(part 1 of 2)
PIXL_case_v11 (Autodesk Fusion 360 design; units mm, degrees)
part number: 0.96Oled_W_4_Buttons
base_feature "Base Feature"
sketch "Sketch2" plane through (-14.9, 0, 0) normal (1, 0, 0) x axis (0, 1, 0)
  line L1 (-22, 2.8) -> (-14, 2.8)
  line L2 (-22, -6.3) -> (-22, 2.8)
  line L3 (-14, -6.3) -> (-22, -6.3)
  line L4 (-14, 2.8) -> (-14, -6.3)
  line L5 (-20.5, -3.5) -> (-15.5, -3.5)
  line L6 (-20.5, 0) -> (-20.5, -3.5)
  line L7 (-15.5, 0) -> (-20.5, 0)
  line L8 (-15.5, -3.5) -> (-15.5, 0)
  horizontal L5
  vertical L6
  horizontal L7
  vertical L8
sketch "Sketch3" plane through (-22.2, 0, 0) normal (1, 0, 0) x axis (0, 1, 0)
  line L1 (12, -6.5) -> (-23.8, -6.5)
  line L2 (12, 2.8) -> (12, -6.5)
  line L3 (-14, 2.8) -> (12, 2.8)
  line L4 (-14, -6.3) -> (-14, 2.8)
  line L5 (-14.9, -6.3) -> (-14, -6.3)
  line L6 (-14.9, 2.8) -> (-14.9, -6.3)
  line L7 (-21.1, 2.8) -> (-14.9, 2.8)
  line L8 (-21.1, -6.3) -> (-21.1, 2.8)
  line L9 (-22, -6.3) -> (-21.1, -6.3)
  line L10 (-22, 2.8) -> (-22, -6.3)
  line L11 (-23.8, 2.8) -> (-22, 2.8)
  line L12 (-23.8, -6.5) -> (-23.8, 2.8)
  line L13 (-13.4, -1.2) -> (-13.4, -3.2)
  line L14 (-7.6, -1.2) -> (-13.4, -1.2)
  line L15 (-7.6, -3.2) -> (-7.6, -1.2)
  line L16 (-13.4, -3.2) -> (-7.6, -3.2)
  line L17 (-15.5, -1) -> (-20.5, -1)
  line L18 (-15.5, -5) -> (-15.5, -1)
  line L19 (-20.5, -5) -> (-15.5, -5)
  line L20 (-20.5, -1) -> (-20.5, -5)
  line L21 (-15.5, -5) -> (-20.5, -1)
  line L22 (-20.5, -5) -> (-15.5, -1)
  point P22 (-18, -3)
  horizontal L17
  perpendicular L17 L18
  parallel L17 L19
  parallel L18 L20
  coincident L21 P22
  coincident L22 P22
sketch "Sketch4" plane through (-24.2, 0, 0) normal (-1, 0, 0) x axis (0, -1, 0)
  line L1 (15.5, -2) -> (15.5, -4)
  line L2 (19.5, -1) -> (16.5, -1)
  line L3 (20.5, -4) -> (20.5, -2)
  line L4 (16.5, -5) -> (19.5, -5)
  line L5 (22.5, -6.5) -> (-10.7, -6.5)
  line L6 (22.5, 3.9) -> (22.5, -6.5)
  line L7 (-10.7, 3.9) -> (22.5, 3.9)
  line L8 (-10.7, -6.5) -> (-10.7, 3.9)
  line L9 (16.5, -4.747) -> (19.5, -4.747)
  line L10 (20.247, -4) -> (20.247, -2)
  line L11 (19.5, -1.253) -> (16.5, -1.253)
  line L12 (15.753, -2) -> (15.753, -4)
  arc A1 centre (16.5, -2) radius 1 clockwise from (15.5, -2) to (16.5, -1)
  arc A2 centre (19.5, -2) radius 1 clockwise from (19.5, -1) to (20.5, -2)
  arc A3 centre (19.5, -4) radius 1 clockwise from (20.5, -4) to (19.5, -5)
  arc A4 centre (16.5, -4) radius 1 clockwise from (16.5, -5) to (15.5, -4)
  arc A5 centre (16.5, -4) radius 0.747 clockwise from (16.5, -4.747) to (15.753, -4)
  arc A6 centre (19.5, -4) radius 0.747 clockwise from (20.247, -4) to (19.5, -4.747)
  arc A7 centre (19.5, -2) radius 0.747 clockwise from (19.5, -1.253) to (20.247, -2)
  arc A8 centre (16.5, -2) radius 0.747 clockwise from (15.753, -2) to (16.5, -1.253)
  dimension "d6918" = 0.253
extrude "Extrude1" new body sketch "Sketch4" profile of A5 L12 L11 L10 L9 A8 A7 A6 against normal blind 2.4
sketch "Sketch5" plane through (-21.8, 0, 0) normal (1, 0, 0) x axis (0, 1, 0)
  line L1 (-16.5, -4.747) -> (-19.5, -4.747)
  line L2 (-15.753, -2) -> (-15.753, -4)
  line L3 (-19.5, -1.253) -> (-16.5, -1.253)
  line L4 (-20.247, -4) -> (-20.247, -2)
  line L5 (-15.2226, -2) -> (-15.2226, -4)
  line L6 (-19.5, -0.7226) -> (-16.5, -0.7226)
  line L7 (-20.7774, -4) -> (-20.7774, -2)
  line L8 (-16.5, -5.2774) -> (-19.5, -5.2774)
  arc A1 centre (-19.5, -4) radius 0.747 clockwise from (-19.5, -4.747) to (-20.247, -4)
  arc A2 centre (-16.5, -4) radius 0.747 clockwise from (-15.753, -4) to (-16.5, -4.747)
  arc A3 centre (-16.5, -2) radius 0.747 clockwise from (-16.5, -1.253) to (-15.753, -2)
  arc A4 centre (-19.5, -2) radius 0.747 clockwise from (-20.247, -2) to (-19.5, -1.253)
  arc A5 centre (-16.5, -2) radius 1.2774 clockwise from (-16.5, -0.7226) to (-15.2226, -2)
  arc A6 centre (-19.5, -2) radius 1.2774 clockwise from (-20.7774, -2) to (-19.5, -0.7226)
  arc A7 centre (-19.5, -4) radius 1.2774 clockwise from (-19.5, -5.2774) to (-20.7774, -4)
  arc A8 centre (-16.5, -4) radius 1.2774 clockwise from (-15.2226, -4) to (-16.5, -5.2774)
  circle C1 centre (-18, -3) radius 0.7
  dimension "d6921" = 0.5304
extrude "Extrude2" add sketch "Sketch5" profile of A1 L1 A2 L2 A3 L3 A4 L4 L8 L6 L5 A8 A7 A6 A5 L7 against normal blind 0.2
extrude "Extrude3" add sketch "Sketch5" profile of C1 along normal blind 0.2
chamfer "Chamfer1" distance 0.2
extrude "Extrude4" add of existing geometry blind 0.6
sketch "Sketch6" plane through (-24.2, 0.0764, 0.0727) normal (-1, 0, 0) x axis (0, -1, 0)
  line L1 (15.5764, -2.0727) -> (15.5764, -4.0727)
  line L2 (19.5764, -1.0727) -> (16.5764, -1.0727)
  line L3 (20.5764, -4.0727) -> (20.5764, -2.0727)
  line L4 (16.5764, -5.0727) -> (19.5764, -5.0727)
  line L5 (22.5764, -6.5727) -> (-10.6236, -6.5727)
  line L6 (22.5764, 3.8273) -> (22.5764, -6.5727)
  line L7 (-10.6236, 3.8273) -> (22.5764, 3.8273)
  line L8 (-10.6236, -6.5727) -> (-10.6236, 3.8273)
  curve K1 (11.5332, -0.4103) -> (11.8143, -0.6915)
  curve K2 (11.252, -0.6915) -> (11.5332, -0.4103)
  line L9 (11.252, -3.2218) -> (11.252, -0.6915)
  curve K3 (11.5332, -3.503) -> (11.252, -3.2218)
  curve K4 (11.8143, -3.2218) -> (11.5332, -3.503)
  line L10 (11.8143, -0.6915) -> (11.8143, -3.2218)
  curve K5 (10.6893, -1.1174) -> (10.5799, -1.4996)
  curve K6 (10.307, -1.0079) -> (10.6893, -1.1174)
  curve K7 (9.0029, -3.2218) -> (10.307, -1.0079)
  curve K8 (11.5332, -5.7521) -> (9.0029, -3.2218)
  curve K9 (14.0635, -3.2218) -> (11.5332, -5.7521)
  curve K10 (12.7985, -1.0302) -> (14.0635, -3.2218)
  curve K11 (12.4144, -1.1328) -> (12.7985, -1.0302)
  curve K12 (12.517, -1.5169) -> (12.4144, -1.1328)
  curve K13 (13.5012, -3.2218) -> (12.517, -1.5169)
  curve K14 (11.5332, -5.1898) -> (13.5012, -3.2218)
  curve K15 (9.5652, -3.2218) -> (11.5332, -5.1898)
  curve K16 (10.5799, -1.4996) -> (9.5652, -3.2218)
  arc A1 centre (16.5764, -2.0727) radius 1 clockwise from (15.5764, -2.0727) to (16.5764, -1.0727)
  arc A2 centre (19.5764, -2.0727) radius 1 clockwise from (19.5764, -1.0727) to (20.5764, -2.0727)
  arc A3 centre (19.5764, -4.0727) radius 1 clockwise from (20.5764, -4.0727) to (19.5764, -5.0727)
  arc A4 centre (16.5764, -4.0727) radius 1 clockwise from (16.5764, -5.0727) to (15.5764, -4.0727)
work_plane "WorkPlane1" AlongDistance -6.5 ExtraOffset 0
sketch "Sketch1" plane through (0, 0, -6.5) normal (0, 0, 1) x axis (1, 0, 0)
  line L1 (24.2, -27.5) -> (-24.2, -27.5)
  line L2 (24.2, 15.7) -> (24.2, -27.5)
  line L3 (-24.2, 15.7) -> (24.2, 15.7)
  line L4 (-24.2, -27.5) -> (-24.2, 15.7)
extrude "Extrude1" new body sketch "Sketch1" along normal blind 11.8
fillet "Fillet1" radius 5
fillet "Fillet2" radius 1.4
work_plane "WorkPlane2" AlongDistance -6.5 ExtraOffset 0
sketch "Sketch2" plane through (0, 0, -6.5) normal (0, 0, 1) x axis (1, 0, 0)
  line L1 (22.2, -25.5) -> (-22.2, -25.5)
  line L2 (22.2, 13.7) -> (22.2, -25.5)
  line L3 (-22.2, 13.7) -> (22.2, 13.7)
  line L4 (-22.2, -25.5) -> (-22.2, 13.7)
extrude "Extrude2" cut sketch "Sketch2" along normal blind 9.3
fillet "Fillet3" radius 1.7
work_plane "WorkPlane3" AlongDistance 2.79 ExtraOffset 0
sketch "Sketch3" plane through (0, 0, 2.79) normal (0, 0, 1) x axis (1, 0, 0)
  line L1 (20.7, -11.3) -> (11, -11.3)
  line L2 (20.7, 11.7) -> (20.7, -11.3)
  line L3 (11, 11.7) -> (20.7, 11.7)
  line L4 (11, -11.3) -> (11, 11.7)
extrude "Extrude3" cut sketch "Sketch3" along normal blind 1.56
work_plane "WorkPlane4" AlongDistance 2.79 ExtraOffset 0
sketch "Sketch4" plane through (0, 0, 2.79) normal (0, 0, 1) x axis (1, 0, 0)
  line L1 (10, 9.6) -> (-10.8, 9.6)
  line L2 (10, 12.2) -> (10, 9.6)
  line L3 (-10.8, 12.2) -> (10, 12.2)
  line L4 (-10.8, 9.6) -> (-10.8, 12.2)
extrude "Extrude4" cut sketch "Sketch4" along normal blind 0.91
work_plane "WorkPlane5" AlongDistance 4.34 ExtraOffset 0
sketch "Sketch5" plane through (0, 0, 4.34) normal (0, 0, 1) x axis (1, 0, 0)
  line L1 (12.1, 5.6) -> (11.5, 5.6)
  line L2 (12.1, 11.8) -> (12.1, 5.6)
  line L3 (11.5, 11.8) -> (12.1, 11.8)
  line L4 (11.5, 5.6) -> (11.5, 11.8)
extrude "Extrude5" cut sketch "Sketch5" along normal blind 1.06
work_plane "WorkPlane6" AlongDistance 4.34 ExtraOffset 0
sketch "Sketch6" plane through (0, 0, 4.34) normal (0, 0, 1) x axis (1, 0, 0)
  line L1 (19.6, 11.2) -> (11.5, 11.2)
  line L2 (19.6, 11.8) -> (19.6, 11.2)
  line L3 (11.5, 11.8) -> (19.6, 11.8)
  line L4 (11.5, 11.2) -> (11.5, 11.8)
extrude "Extrude6" cut sketch "Sketch6" along normal blind 1.06
work_plane "WorkPlane7" AlongDistance 4.34 ExtraOffset 0
sketch "Sketch7" plane through (0, 0, 4.34) normal (0, 0, 1) x axis (1, 0, 0)
  line L1 (19.6, 5.6) -> (11.5, 5.6)
  line L2 (19.6, 6.2) -> (19.6, 5.6)
  line L3 (11.5, 6.2) -> (19.6, 6.2)
  line L4 (11.5, 5.6) -> (11.5, 6.2)
extrude "Extrude7" cut sketch "Sketch7" along normal blind 1.06
work_plane "WorkPlane8" AlongDistance 4.34 ExtraOffset 0
sketch "Sketch8" plane through (0, 0, 4.34) normal (0, 0, 1) x axis (1, 0, 0)
  line L1 (12.1, -0.07) -> (11.5, -0.07)
  line L2 (12.1, 6.13) -> (12.1, -0.07)
  line L3 (11.5, 6.13) -> (12.1, 6.13)
  line L4 (11.5, -0.07) -> (11.5, 6.13)
extrude "Extrude8" cut sketch "Sketch8" along normal blind 1.06
work_plane "WorkPlane9" AlongDistance 4.34 ExtraOffset 0
sketch "Sketch9" plane through (0, 0, 4.34) normal (0, 0, 1) x axis (1, 0, 0)
  line L1 (19.6, 5.53) -> (11.5, 5.53)
  line L2 (19.6, 6.13) -> (19.6, 5.53)
  line L3 (11.5, 6.13) -> (19.6, 6.13)
  line L4 (11.5, 5.53) -> (11.5, 6.13)
extrude "Extrude9" cut sketch "Sketch9" along normal blind 1.06
work_plane "WorkPlane10" AlongDistance 4.34 ExtraOffset 0
sketch "Sketch10" plane through (0, 0, 4.34) normal (0, 0, 1) x axis (1, 0, 0)
  line L1 (19.6, -0.07) -> (11.5, -0.07)
  line L2 (19.6, 0.53) -> (19.6, -0.07)
  line L3 (11.5, 0.53) -> (19.6, 0.53)
  line L4 (11.5, -0.07) -> (11.5, 0.53)
extrude "Extrude10" cut sketch "Sketch10" along normal blind 1.06
work_plane "WorkPlane11" AlongDistance 4.34 ExtraOffset 0
sketch "Sketch11" plane through (0, 0, 4.34) normal (0, 0, 1) x axis (1, 0, 0)
  line L1 (12.1, -5.73) -> (11.5, -5.73)
  line L2 (12.1, 0.47) -> (12.1, -5.73)
  line L3 (11.5, 0.47) -> (12.1, 0.47)
  line L4 (11.5, -5.73) -> (11.5, 0.47)
extrude "Extrude11" cut sketch "Sketch11" along normal blind 1.06
work_plane "WorkPlane12" AlongDistance 4.34 ExtraOffset 0
sketch "Sketch12" plane through (0, 0, 4.34) normal (0, 0, 1) x axis (1, 0, 0)
  line L1 (19.6, -0.13) -> (11.5, -0.13)
  line L2 (19.6, 0.47) -> (19.6, -0.13)
  line L3 (11.5, 0.47) -> (19.6, 0.47)
  line L4 (11.5, -0.13) -> (11.5, 0.47)
extrude "Extrude12" cut sketch "Sketch12" along normal blind 1.06
work_plane "WorkPlane13" AlongDistance 4.34 ExtraOffset 0
sketch "Sketch13" plane through (0, 0, 4.34) normal (0, 0, 1) x axis (1, 0, 0)
  line L1 (19.6, -5.73) -> (11.5, -5.73)
  line L2 (19.6, -5.13) -> (19.6, -5.73)
  line L3 (11.5, -5.13) -> (19.6, -5.13)
  line L4 (11.5, -5.73) -> (11.5, -5.13)
extrude "Extrude13" cut sketch "Sketch13" along normal blind 1.06
work_plane "WorkPlane14" AlongDistance 4.34 ExtraOffset 0
sketch "Sketch14" plane through (0, 0, 4.34) normal (0, 0, 1) x axis (1, 0, 0)
  line L1 (12.1, -11.4) -> (11.5, -11.4)
  line L2 (12.1, -5.2) -> (12.1, -11.4)
  line L3 (11.5, -5.2) -> (12.1, -5.2)
  line L4 (11.5, -11.4) -> (11.5, -5.2)
extrude "Extrude14" cut sketch "Sketch14" along normal blind 1.06
work_plane "WorkPlane15" AlongDistance 4.34 ExtraOffset 0
sketch "Sketch15" plane through (0, 0, 4.34) normal (0, 0, 1) x axis (1, 0, 0)
  line L1 (19.6, -5.8) -> (11.5, -5.8)
  line L2 (19.6, -5.2) -> (19.6, -5.8)
  line L3 (11.5, -5.2) -> (19.6, -5.2)
  line L4 (11.5, -5.8) -> (11.5, -5.2)
extrude "Extrude15" cut sketch "Sketch15" along normal blind 1.06
work_plane "WorkPlane16" AlongDistance 4.34 ExtraOffset 0
sketch "Sketch16" plane through (0, 0, 4.34) normal (0, 0, 1) x axis (1, 0, 0)
  line L1 (19.6, -11.4) -> (11.5, -11.4)
  line L2 (19.6, -10.8) -> (19.6, -11.4)
  line L3 (11.5, -10.8) -> (19.6, -10.8)
  line L4 (11.5, -11.4) -> (11.5, -10.8)
extrude "Extrude16" cut sketch "Sketch16" along normal blind 1.06
work_plane "WorkPlane17" AlongDistance 4.34 ExtraOffset 0
sketch "Sketch17" plane through (0, 0, 4.34) normal (0, 0, 1) x axis (1, 0, 0)
  line L1 (20.7, 6.2) -> (18.4, 6.2)
  line L2 (20.7, 11.2) -> (20.7, 6.2)
  line L3 (18.4, 11.2) -> (20.7, 11.2)
  line L4 (18.4, 6.2) -> (18.4, 11.2)
extrude "Extrude17" cut sketch "Sketch17" along normal blind 0.46
work_plane "WorkPlane18" AlongDistance 4.34 ExtraOffset 0
sketch "Sketch18" plane through (0, 0, 4.34) normal (0, 0, 1) x axis (1, 0, 0)
  line L1 (20.7, 0.53) -> (18.4, 0.53)
  line L2 (20.7, 5.53) -> (20.7, 0.53)
  line L3 (18.4, 5.53) -> (20.7, 5.53)
  line L4 (18.4, 0.53) -> (18.4, 5.53)
extrude "Extrude18" cut sketch "Sketch18" along normal blind 0.46
work_plane "WorkPlane19" AlongDistance 4.34 ExtraOffset 0
sketch "Sketch19" plane through (0, 0, 4.34) normal (0, 0, 1) x axis (1, 0, 0)
  line L1 (20.7, -5.13) -> (18.4, -5.13)
  line L2 (20.7, -0.13) -> (20.7, -5.13)
  line L3 (18.4, -0.13) -> (20.7, -0.13)
  line L4 (18.4, -5.13) -> (18.4, -0.13)
extrude "Extrude19" cut sketch "Sketch19" along normal blind 0.46
work_plane "WorkPlane20" AlongDistance 4.34 ExtraOffset 0
sketch "Sketch20" plane through (0, 0, 4.34) normal (0, 0, 1) x axis (1, 0, 0)
  line L1 (20.7, -10.8) -> (18.4, -10.8)
  line L2 (20.7, -5.8) -> (20.7, -10.8)
  line L3 (18.4, -5.8) -> (20.7, -5.8)
  line L4 (18.4, -10.8) -> (18.4, -5.8)
extrude "Extrude20" cut sketch "Sketch20" along normal blind 0.46
work_plane "WorkPlane21" AlongDistance 2.79 ExtraOffset 0
sketch "Sketch21" plane through (0, 0, 2.79) normal (0, 0, 1) x axis (1, 0, 0)
  line L1 (7, -6.6) -> (-16.3, -6.6)
  line L2 (7, 6.4) -> (7, -6.6)
  line L3 (-16.3, 6.4) -> (7, 6.4)
  line L4 (-16.3, -6.6) -> (-16.3, 6.4)
extrude "Extrude21" cut sketch "Sketch21" along normal blind 2.61
chamfer "Chamfer1" distance 1.2
work_plane "WorkPlane22" AlongDistance 1.6 ExtraOffset 0
sketch "Sketch22" plane through (0, 0, 1.6) normal (0, 0, 1) x axis (1, 0, 0)
  circle C1 centre (-20.5, -12) radius 1.5
extrude "Extrude22" add sketch "Sketch22" along normal blind 1.21
work_plane "WorkPlane23" AlongDistance 1.6 ExtraOffset 0
sketch "Sketch23" plane through (0, 0, 1.6) normal (0, 0, 1) x axis (1, 0, 0)
  circle C1 centre (-20.5, 12) radius 1.5
extrude "Extrude23" add sketch "Sketch23" along normal blind 1.21
work_plane "WorkPlane24" AlongDistance 1.6 ExtraOffset 0
sketch "Sketch24" plane through (0, 0, 1.6) normal (0, 0, 1) x axis (1, 0, 0)
  circle C1 centre (20.5, -12) radius 1.5
extrude "Extrude24" add sketch "Sketch24" along normal blind 1.21
work_plane "WorkPlane25" AlongDistance 1.6 ExtraOffset 0
sketch "Sketch25" plane through (0, 0, 1.6) normal (0, 0, 1) x axis (1, 0, 0)
  circle C1 centre (20.5, 12) radius 1.5
extrude "Extrude25" add sketch "Sketch25" along normal blind 1.21
work_plane "WorkPlane26" AlongDistance 5.3 ExtraOffset 0
sketch "Sketch26" plane through (0, 0, 5.3) normal (0, 0, 1) x axis (1, 0, 0)
  line L1 (-16.5, -17.8) -> (-19.8, -17.8)
  line L2 (-16.5, -16.7) -> (-16.5, -17.8)
  line L3 (-19.8, -16.7) -> (-16.5, -16.7)
  line L4 (-19.8, -17.8) -> (-19.8, -16.7)
  line L5 (-18.7, -18.9) -> (-19.8, -18.9)
  line L6 (-18.7, -17.8) -> (-18.7, -18.9)
  line L7 (-19.8, -17.8) -> (-18.7, -17.8)
  line L8 (-19.8, -18.9) -> (-19.8, -17.8)
  line L9 (-15.4, -18.9) -> (-16.5, -18.9)
  line L10 (-15.4, -17.8) -> (-15.4, -18.9)
  line L11 (-16.5, -17.8) -> (-15.4, -17.8)
  line L12 (-16.5, -18.9) -> (-16.5, -17.8)
  line L13 (-18.7, -20) -> (-19.8, -20)
  line L14 (-18.7, -18.9) -> (-18.7, -20)
  line L15 (-19.8, -18.9) -> (-18.7, -18.9)
  line L16 (-19.8, -20) -> (-19.8, -18.9)
  line L17 (-15.4, -20) -> (-16.5, -20)
  line L18 (-15.4, -18.9) -> (-15.4, -20)
  line L19 (-16.5, -18.9) -> (-15.4, -18.9)
  line L20 (-16.5, -20) -> (-16.5, -18.9)
  line L21 (-16.5, -21.1) -> (-19.8, -21.1)
  line L22 (-16.5, -20) -> (-16.5, -21.1)
  line L23 (-19.8, -20) -> (-16.5, -20)
  line L24 (-19.8, -21.1) -> (-19.8, -20)
  line L25 (-18.7, -22.2) -> (-19.8, -22.2)
  line L26 (-18.7, -21.1) -> (-18.7, -22.2)
  line L27 (-19.8, -21.1) -> (-18.7, -21.1)
  line L28 (-19.8, -22.2) -> (-19.8, -21.1)
  line L29 (-18.7, -23.3) -> (-19.8, -23.3)
  line L30 (-18.7, -22.2) -> (-18.7, -23.3)
  line L31 (-19.8, -22.2) -> (-18.7, -22.2)
  line L32 (-19.8, -23.3) -> (-19.8, -22.2)
  line L33 (-13.2, -17.8) -> (-14.3, -17.8)
  line L34 (-13.2, -16.7) -> (-13.2, -17.8)
  line L35 (-14.3, -16.7) -> (-13.2, -16.7)
  line L36 (-14.3, -17.8) -> (-14.3, -16.7)
  line L37 (-13.2, -20) -> (-14.3, -20)
  line L38 (-13.2, -18.9) -> (-13.2, -20)
  line L39 (-14.3, -18.9) -> (-13.2, -18.9)
  line L40 (-14.3, -20) -> (-14.3, -18.9)
  line L41 (-13.2, -21.1) -> (-14.3, -21.1)
  line L42 (-13.2, -20) -> (-13.2, -21.1)
  line L43 (-14.3, -20) -> (-13.2, -20)
  line L44 (-14.3, -21.1) -> (-14.3, -20)
  line L45 (-13.2, -22.2) -> (-14.3, -22.2)
  line L46 (-13.2, -21.1) -> (-13.2, -22.2)
  line L47 (-14.3, -21.1) -> (-13.2, -21.1)
  line L48 (-14.3, -22.2) -> (-14.3, -21.1)
  line L49 (-13.2, -23.3) -> (-14.3, -23.3)
  line L50 (-13.2, -22.2) -> (-13.2, -23.3)
  line L51 (-14.3, -22.2) -> (-13.2, -22.2)
  line L52 (-14.3, -23.3) -> (-14.3, -22.2)
  line L53 (-11, -17.8) -> (-12.1, -17.8)
  line L54 (-11, -16.7) -> (-11, -17.8)
  line L55 (-12.1, -16.7) -> (-11, -16.7)
  line L56 (-12.1, -17.8) -> (-12.1, -16.7)
  line L57 (-7.7, -17.8) -> (-8.8, -17.8)
  line L58 (-7.7, -16.7) -> (-7.7, -17.8)
  line L59 (-8.8, -16.7) -> (-7.7, -16.7)
  line L60 (-8.8, -17.8) -> (-8.8, -16.7)
  line L61 (-11, -18.9) -> (-12.1, -18.9)
  line L62 (-11, -17.8) -> (-11, -18.9)
  line L63 (-12.1, -17.8) -> (-11, -17.8)
  line L64 (-12.1, -18.9) -> (-12.1, -17.8)
  line L65 (-7.7, -18.9) -> (-8.8, -18.9)
  line L66 (-7.7, -17.8) -> (-7.7, -18.9)
  line L67 (-8.8, -17.8) -> (-7.7, -17.8)
  line L68 (-8.8, -18.9) -> (-8.8, -17.8)
  line L69 (-8.8, -20) -> (-11, -20)
  line L70 (-8.8, -18.9) -> (-8.8, -20)
  line L71 (-11, -18.9) -> (-8.8, -18.9)
  line L72 (-11, -20) -> (-11, -18.9)
  line L73 (-8.8, -21.1) -> (-11, -21.1)
  line L74 (-8.8, -20) -> (-8.8, -21.1)
  line L75 (-11, -20) -> (-8.8, -20)
  line L76 (-11, -21.1) -> (-11, -20)
  line L77 (-11, -22.2) -> (-12.1, -22.2)
  line L78 (-11, -21.1) -> (-11, -22.2)
  line L79 (-12.1, -21.1) -> (-11, -21.1)
  line L80 (-12.1, -22.2) -> (-12.1, -21.1)
  line L81 (-7.7, -22.2) -> (-8.8, -22.2)
  line L82 (-7.7, -21.1) -> (-7.7, -22.2)
  line L83 (-8.8, -21.1) -> (-7.7, -21.1)
  line L84 (-8.8, -22.2) -> (-8.8, -21.1)
  line L85 (-11, -23.3) -> (-12.1, -23.3)
  line L86 (-11, -22.2) -> (-11, -23.3)
  line L87 (-12.1, -22.2) -> (-11, -22.2)
  line L88 (-12.1, -23.3) -> (-12.1, -22.2)
  line L89 (-7.7, -23.3) -> (-8.8, -23.3)
  line L90 (-7.7, -22.2) -> (-7.7, -23.3)
  line L91 (-8.8, -22.2) -> (-7.7, -22.2)
  line L92 (-8.8, -23.3) -> (-8.8, -22.2)
  line L93 (-5.5, -17.8) -> (-6.6, -17.8)
  line L94 (-5.5, -16.7) -> (-5.5, -17.8)
  line L95 (-6.6, -16.7) -> (-5.5, -16.7)
  line L96 (-6.6, -17.8) -> (-6.6, -16.7)
  line L97 (-5.5, -18.9) -> (-6.6, -18.9)
  line L98 (-5.5, -17.8) -> (-5.5, -18.9)
  line L99 (-6.6, -17.8) -> (-5.5, -17.8)
  line L100 (-6.6, -18.9) -> (-6.6, -17.8)
  line L101 (-5.5, -20) -> (-6.6, -20)
  line L102 (-5.5, -18.9) -> (-5.5, -20)
  line L103 (-6.6, -18.9) -> (-5.5, -18.9)
  line L104 (-6.6, -20) -> (-6.6, -18.9)
  line L105 (-5.5, -21.1) -> (-6.6, -21.1)
  line L106 (-5.5, -20) -> (-5.5, -21.1)
  line L107 (-6.6, -20) -> (-5.5, -20)
  line L108 (-6.6, -21.1) -> (-6.6, -20)
  line L109 (-5.5, -22.2) -> (-6.6, -22.2)
  line L110 (-5.5, -21.1) -> (-5.5, -22.2)
  line L111 (-6.6, -21.1) -> (-5.5, -21.1)
  line L112 (-6.6, -22.2) -> (-6.6, -21.1)
  line L113 (-2.2, -23.3) -> (-6.6, -23.3)
  line L114 (-2.2, -22.2) -> (-2.2, -23.3)
  line L115 (-6.6, -22.2) -> (-2.2, -22.2)
  line L116 (-6.6, -23.3) -> (-6.6, -22.2)
extrude "Extrude26" cut sketch "Sketch26" against normal blind 0.4
work_plane "WorkPlane27" AlongDistance 5.3 ExtraOffset 0
sketch "Sketch27" plane through (0, 0, 5.3) normal (0, 0, 1) x axis (1, 0, 0)
  line L1 (3.25, -22.25) -> (2.5, -22.25)
  line L2 (3.25, -21.5) -> (3.25, -22.25)
  line L3 (2.5, -21.5) -> (3.25, -21.5)
  line L4 (2.5, -22.25) -> (2.5, -21.5)
  line L5 (4.5, -22.25) -> (3.75, -22.25)
  line L6 (4.5, -21.5) -> (4.5, -22.25)
  line L7 (3.75, -21.5) -> (4.5, -21.5)
  line L8 (3.75, -22.25) -> (3.75, -21.5)
  line L9 (5.75, -22.25) -> (5, -22.25)
  line L10 (5.75, -21.5) -> (5.75, -22.25)
  line L11 (5, -21.5) -> (5.75, -21.5)
  line L12 (5, -22.25) -> (5, -21.5)
  line L13 (7, -22.25) -> (6.25, -22.25)
  line L14 (7, -21.5) -> (7, -22.25)
  line L15 (6.25, -21.5) -> (7, -21.5)
  line L16 (6.25, -22.25) -> (6.25, -21.5)
  line L17 (8.25, -22.25) -> (7.5, -22.25)
  line L18 (8.25, -21.5) -> (8.25, -22.25)
  line L19 (7.5, -21.5) -> (8.25, -21.5)
  line L20 (7.5, -22.25) -> (7.5, -21.5)
  line L21 (9.5, -22.25) -> (8.75, -22.25)
  line L22 (9.5, -21.5) -> (9.5, -22.25)
  line L23 (8.75, -21.5) -> (9.5, -21.5)
  line L24 (8.75, -22.25) -> (8.75, -21.5)
  line L25 (10.75, -22.25) -> (10, -22.25)
  line L26 (10.75, -21.5) -> (10.75, -22.25)
  line L27 (10, -21.5) -> (10.75, -21.5)
  line L28 (10, -22.25) -> (10, -21.5)
  line L29 (13.25, -22.25) -> (12.5, -22.25)
  line L30 (13.25, -21.5) -> (13.25, -22.25)
  line L31 (12.5, -21.5) -> (13.25, -21.5)
  line L32 (12.5, -22.25) -> (12.5, -21.5)
  line L33 (15.75, -22.25) -> (15, -22.25)
  line L34 (15.75, -21.5) -> (15.75, -22.25)
  line L35 (15, -21.5) -> (15.75, -21.5)
  line L36 (15, -22.25) -> (15, -21.5)
  line L37 (3.25, -21) -> (2.5, -21)
  line L38 (3.25, -20.25) -> (3.25, -21)
  line L39 (2.5, -20.25) -> (3.25, -20.25)
  line L40 (2.5, -21) -> (2.5, -20.25)
  line L41 (4.5, -21) -> (3.75, -21)
  line L42 (4.5, -20.25) -> (4.5, -21)
  line L43 (3.75, -20.25) -> (4.5, -20.25)
  line L44 (3.75, -21) -> (3.75, -20.25)
  line L45 (7, -21) -> (6.25, -21)
  line L46 (7, -20.25) -> (7, -21)
  line L47 (6.25, -20.25) -> (7, -20.25)
  line L48 (6.25, -21) -> (6.25, -20.25)
  line L49 (9.5, -21) -> (8.75, -21)
  line L50 (9.5, -20.25) -> (9.5, -21)
  line L51 (8.75, -20.25) -> (9.5, -20.25)
  line L52 (8.75, -21) -> (8.75, -20.25)
  line L53 (12, -21) -> (11.25, -21)
  line L54 (12, -20.25) -> (12, -21)
  line L55 (11.25, -20.25) -> (12, -20.25)
  line L56 (11.25, -21) -> (11.25, -20.25)
  line L57 (3.25, -19.75) -> (2.5, -19.75)
  line L58 (3.25, -19) -> (3.25, -19.75)
  line L59 (2.5, -19) -> (3.25, -19)
  line L60 (2.5, -19.75) -> (2.5, -19)
  line L61 (4.5, -19.75) -> (3.75, -19.75)
  line L62 (4.5, -19) -> (4.5, -19.75)
  line L63 (3.75, -19) -> (4.5, -19)
  line L64 (3.75, -19.75) -> (3.75, -19)
  line L65 (5.75, -19.75) -> (5, -19.75)
  line L66 (5.75, -19) -> (5.75, -19.75)
  line L67 (5, -19) -> (5.75, -19)
  line L68 (5, -19.75) -> (5, -19)
  line L69 (7, -19.75) -> (6.25, -19.75)
  line L70 (7, -19) -> (7, -19.75)
  line L71 (6.25, -19) -> (7, -19)
  line L72 (6.25, -19.75) -> (6.25, -19)
  line L73 (8.25, -19.75) -> (7.5, -19.75)
  line L74 (8.25, -19) -> (8.25, -19.75)
  line L75 (7.5, -19) -> (8.25, -19)
  line L76 (7.5, -19.75) -> (7.5, -19)
  line L77 (10.75, -19.75) -> (10, -19.75)
  line L78 (10.75, -19) -> (10.75, -19.75)
  line L79 (10, -19) -> (10.75, -19)
  line L80 (10, -19.75) -> (10, -19)
  line L81 (13.25, -19.75) -> (12.5, -19.75)
  line L82 (13.25, -19) -> (13.25, -19.75)
  line L83 (12.5, -19) -> (13.25, -19)
  line L84 (12.5, -19.75) -> (12.5, -19)
  line L85 (15.75, -19.75) -> (15, -19.75)
  line L86 (15.75, -19) -> (15.75, -19.75)
  line L87 (15, -19) -> (15.75, -19)
  line L88 (15, -19.75) -> (15, -19)
  line L89 (3.25, -18.5) -> (2.5, -18.5)
  line L90 (3.25, -17.75) -> (3.25, -18.5)
  line L91 (2.5, -17.75) -> (3.25, -17.75)
  line L92 (2.5, -18.5) -> (2.5, -17.75)
  line L93 (4.5, -18.5) -> (3.75, -18.5)
  line L94 (4.5, -17.75) -> (4.5, -18.5)
  line L95 (3.75, -17.75) -> (4.5, -17.75)
  line L96 (3.75, -18.5) -> (3.75, -17.75)
  line L97 (7, -18.5) -> (6.25, -18.5)
  line L98 (7, -17.75) -> (7, -18.5)
  line L99 (6.25, -17.75) -> (7, -17.75)
  line L100 (6.25, -18.5) -> (6.25, -17.75)
  line L101 (9.5, -18.5) -> (8.75, -18.5)
  line L102 (9.5, -17.75) -> (9.5, -18.5)
  line L103 (8.75, -17.75) -> (9.5, -17.75)
  line L104 (8.75, -18.5) -> (8.75, -17.75)
  line L105 (12, -18.5) -> (11.25, -18.5)
  line L106 (12, -17.75) -> (12, -18.5)
  line L107 (11.25, -17.75) -> (12, -17.75)
  line L108 (11.25, -18.5) -> (11.25, -17.75)
extrude "Extrude27" cut sketch "Sketch27" against normal blind 0.35
work_plane "WorkPlane28" AlongDistance 5.3 ExtraOffset 0
sketch "Sketch28" plane through (0, 0, 5.3) normal (0, 0, 1) x axis (1, 0, 0)
  line L1 (17.125, 9.375) -> (16.675, 9.375)
  line L2 (17.125, 9.825) -> (17.125, 9.375)
  line L3 (16.675, 9.825) -> (17.125, 9.825)
  line L4 (16.675, 9.375) -> (16.675, 9.825)
  line L5 (17.575, 8.925) -> (16.225, 8.925)
  line L6 (17.575, 9.375) -> (17.575, 8.925)
  line L7 (16.225, 9.375) -> (17.575, 9.375)
  line L8 (16.225, 8.925) -> (16.225, 9.375)
  line L9 (16.675, 8.475) -> (15.775, 8.475)
  line L10 (16.675, 8.925) -> (16.675, 8.475)
  line L11 (15.775, 8.925) -> (16.675, 8.925)
  line L12 (15.775, 8.475) -> (15.775, 8.925)
  line L13 (18.025, 8.475) -> (17.125, 8.475)
  line L14 (18.025, 8.925) -> (18.025, 8.475)
  line L15 (17.125, 8.925) -> (18.025, 8.925)
  line L16 (17.125, 8.475) -> (17.125, 8.925)
  line L17 (16.225, 8.025) -> (15.325, 8.025)
  line L18 (16.225, 8.475) -> (16.225, 8.025)
  line L19 (15.325, 8.475) -> (16.225, 8.475)
  line L20 (15.325, 8.025) -> (15.325, 8.475)
  line L21 (18.475, 8.025) -> (17.575, 8.025)
  line L22 (18.475, 8.475) -> (18.475, 8.025)
  line L23 (17.575, 8.475) -> (18.475, 8.475)
  line L24 (17.575, 8.025) -> (17.575, 8.475)
  line L25 (15.775, 7.575) -> (15.325, 7.575)
  line L26 (15.775, 8.025) -> (15.775, 7.575)
  line L27 (15.325, 8.025) -> (15.775, 8.025)
  line L28 (15.325, 7.575) -> (15.325, 8.025)
  line L29 (18.475, 7.575) -> (18.025, 7.575)
  line L30 (18.475, 8.025) -> (18.475, 7.575)
  line L31 (18.025, 8.025) -> (18.475, 8.025)
  line L32 (18.025, 7.575) -> (18.025, 8.025)
  line L33 (15.775, 3.705) -> (15.325, 3.705)
  line L34 (15.775, 4.155) -> (15.775, 3.705)
  line L35 (15.325, 4.155) -> (15.775, 4.155)
  line L36 (15.325, 3.705) -> (15.325, 4.155)
  line L37 (18.475, 3.705) -> (18.025, 3.705)
  line L38 (18.475, 4.155) -> (18.475, 3.705)
  line L39 (18.025, 4.155) -> (18.475, 4.155)
  line L40 (18.025, 3.705) -> (18.025, 4.155)
  line L41 (16.225, 3.255) -> (15.325, 3.255)
  line L42 (16.225, 3.705) -> (16.225, 3.255)
  line L43 (15.325, 3.705) -> (16.225, 3.705)
  line L44 (15.325, 3.255) -> (15.325, 3.705)
  line L45 (18.475, 3.255) -> (17.575, 3.255)
  line L46 (18.475, 3.705) -> (18.475, 3.255)
  line L47 (17.575, 3.705) -> (18.475, 3.705)
  line L48 (17.575, 3.255) -> (17.575, 3.705)
  line L49 (16.675, 2.805) -> (15.775, 2.805)
  line L50 (16.675, 3.255) -> (16.675, 2.805)
  line L51 (15.775, 3.255) -> (16.675, 3.255)
  line L52 (15.775, 2.805) -> (15.775, 3.255)
  line L53 (18.025, 2.805) -> (17.125, 2.805)
  line L54 (18.025, 3.255) -> (18.025, 2.805)
  line L55 (17.125, 3.255) -> (18.025, 3.255)
  line L56 (17.125, 2.805) -> (17.125, 3.255)
  line L57 (17.575, 2.355) -> (16.225, 2.355)
  line L58 (17.575, 2.805) -> (17.575, 2.355)
  line L59 (16.225, 2.805) -> (17.575, 2.805)
  line L60 (16.225, 2.355) -> (16.225, 2.805)
  line L61 (17.125, 1.905) -> (16.675, 1.905)
  line L62 (17.125, 2.355) -> (17.125, 1.905)
  line L63 (16.675, 2.355) -> (17.125, 2.355)
  line L64 (16.675, 1.905) -> (16.675, 2.355)
  line L65 (18.475, -1.955) -> (15.325, -1.955)
  line L66 (18.475, -1.505) -> (18.475, -1.955)
  line L67 (15.325, -1.505) -> (18.475, -1.505)
  line L68 (15.325, -1.955) -> (15.325, -1.505)
  line L69 (18.475, -2.855) -> (15.325, -2.855)
  line L70 (18.475, -2.405) -> (18.475, -2.855)
  line L71 (15.325, -2.405) -> (18.475, -2.405)
  line L72 (15.325, -2.855) -> (15.325, -2.405)
  line L73 (18.475, -3.755) -> (15.325, -3.755)
  line L74 (18.475, -3.305) -> (18.475, -3.755)
  line L75 (15.325, -3.305) -> (18.475, -3.305)
  line L76 (15.325, -3.755) -> (15.325, -3.305)
  line L77 (16.675, -7.175) -> (16.225, -7.175)
  line L78 (16.675, -6.725) -> (16.675, -7.175)
  line L79 (16.225, -6.725) -> (16.675, -6.725)
  line L80 (16.225, -7.175) -> (16.225, -6.725)
  line L81 (16.675, -7.625) -> (15.775, -7.625)
  line L82 (16.675, -7.175) -> (16.675, -7.625)
  line L83 (15.775, -7.175) -> (16.675, -7.175)
  line L84 (15.775, -7.625) -> (15.775, -7.175)
  line L85 (18.025, -8.075) -> (15.325, -8.075)
  line L86 (18.025, -7.625) -> (18.025, -8.075)
  line L87 (15.325, -7.625) -> (18.025, -7.625)
  line L88 (15.325, -8.075) -> (15.325, -7.625)
  line L89 (16.675, -8.525) -> (15.775, -8.525)
  line L90 (16.675, -8.075) -> (16.675, -8.525)
  line L91 (15.775, -8.075) -> (16.675, -8.075)
  line L92 (15.775, -8.525) -> (15.775, -8.075)
  line L93 (18.475, -8.525) -> (18.025, -8.525)
  line L94 (18.475, -8.075) -> (18.475, -8.525)
  line L95 (18.025, -8.075) -> (18.475, -8.075)
  line L96 (18.025, -8.525) -> (18.025, -8.075)
  line L97 (16.675, -8.975) -> (16.225, -8.975)
  line L98 (16.675, -8.525) -> (16.675, -8.975)
  line L99 (16.225, -8.525) -> (16.675, -8.525)
  line L100 (16.225, -8.975) -> (16.225, -8.525)
  line L101 (18.475, -8.975) -> (18.025, -8.975)
  line L102 (18.475, -8.525) -> (18.475, -8.975)
  line L103 (18.025, -8.525) -> (18.475, -8.525)
  line L104 (18.025, -8.975) -> (18.025, -8.525)
  line L105 (18.475, -9.425) -> (18.025, -9.425)
  line L106 (18.475, -8.975) -> (18.475, -9.425)
  line L107 (18.025, -8.975) -> (18.475, -8.975)
  line L108 (18.025, -9.425) -> (18.025, -8.975)
  line L109 (18.025, -9.875) -> (15.775, -9.875)
  line L110 (18.025, -9.425) -> (18.025, -9.875)
  line L111 (15.775, -9.425) -> (18.025, -9.425)
  line L112 (15.775, -9.875) -> (15.775, -9.425)
extrude "Extrude28" cut sketch "Sketch28" against normal blind 0.3
work_plane "WorkPlane29" AlongDistance -4.9 ExtraOffset 0
sketch "Sketch29" plane through (0, 0, -4.9) normal (0, 0, 1) x axis (1, 0, 0)
  line L1 (24.7, -21) -> (21.7, -21)
  line L2 (24.7, -11) -> (24.7, -21)
  line L3 (21.7, -11) -> (24.7, -11)
  line L4 (21.7, -21) -> (21.7, -11)
extrude "Extrude29" cut sketch "Sketch29" along normal blind 4
work_plane "WorkPlane30" AlongDistance -5.9 ExtraOffset 0
sketch "Sketch30" plane through (0, 0, -5.9) normal (0, 0, 1) x axis (1, 0, 0)
  line L1 (24.7, -22.5) -> (23.2, -22.5)
  line L2 (24.7, -9.5) -> (24.7, -22.5)
  line L3 (23.2, -9.5) -> (24.7, -9.5)
  line L4 (23.2, -22.5) -> (23.2, -9.5)
extrude "Extrude30" cut sketch "Sketch30" along normal blind 6
work_plane "WorkPlane31" AlongDistance -3.2 ExtraOffset 0
sketch "Sketch31" plane through (0, 0, -3.2) normal (0, 0, 1) x axis (1, 0, 0)
  line L1 (-22.2, -20.4) -> (-22.81, -20.4)
  line L2 (-22.2, -13.6) -> (-22.2, -20.4)
  line L3 (-22.81, -13.6) -> (-22.2, -13.6)
  line L4 (-22.81, -20.4) -> (-22.81, -13.6)
extrude "Extrude31" cut sketch "Sketch31" along normal blind 2
work_plane "WorkPlane32" AlongDistance -3.2 ExtraOffset 0
sketch "Sketch32" plane through (0, 0, -3.2) normal (0, 0, 1) x axis (1, 0, 0)
  line L1 (22.81, -7.2) -> (22.2, -7.2)
  line L2 (22.81, -0.8) -> (22.81, -7.2)
  line L3 (22.2, -0.8) -> (22.81, -0.8)
  line L4 (22.2, -7.2) -> (22.2, -0.8)
extrude "Extrude32" cut sketch "Sketch32" along normal blind 2
work_plane "WorkPlane33" AlongDistance -6 ExtraOffset 0
sketch "Sketch33" plane through (0, 0, -6) normal (0, 0, 1) x axis (1, 0, 0)
  line L1 (19.4, 13.6) -> (10.6, 13.6)
  line L2 (19.4, 14.6) -> (19.4, 13.6)
  line L3 (10.6, 14.6) -> (19.4, 14.6)
  line L4 (10.6, 13.6) -> (10.6, 14.6)
extrude "Extrude33" cut sketch "Sketch33" along normal blind 1.2
work_plane "WorkPlane34" AlongDistance -6.5 ExtraOffset 0
sketch "Sketch34" plane through (0, 0, -6.5) normal (0, 0, 1) x axis (1, 0, 0)
  line L1 (-10.2, -32.1) -> (-12.6, -32.1)
  line L2 (-10.2, -26.5) -> (-10.2, -32.1)
  line L3 (-12.6, -26.5) -> (-10.2, -26.5)
  line L4 (-12.6, -32.1) -> (-12.6, -26.5)
extrude "Extrude34" add sketch "Sketch34" along normal blind 3
work_plane "WorkPlane35" AlongDistance -9.2 ExtraOffset 0
sketch "Sketch35" plane through (0, 0, -9.2) normal (0, 0, 1) x axis (1, 0, 0)
  line L1 (-10.2, -32.1) -> (-12.6, -32.1)
  line L2 (-10.2, -27.7) -> (-10.2, -32.1)
  line L3 (-12.6, -27.7) -> (-10.2, -27.7)
  line L4 (-12.6, -32.1) -> (-12.6, -27.7)
extrude "Extrude35" add sketch "Sketch35" along normal blind 2.71
work_plane "WorkPlane36" AlongDistance -6.5 ExtraOffset 0
sketch "Sketch36" plane through (0, 0, -6.5) normal (0, 0, 1) x axis (1, 0, 0)
  line L1 (-10.2, 14.7) -> (-12.6, 14.7)
  line L2 (-10.2, 20.3) -> (-10.2, 14.7)
  line L3 (-12.6, 20.3) -> (-10.2, 20.3)
  line L4 (-12.6, 14.7) -> (-12.6, 20.3)
extrude "Extrude36" add sketch "Sketch36" along normal blind 3
work_plane "WorkPlane37" AlongDistance -9.2 ExtraOffset 0
sketch "Sketch37" plane through (0, 0, -9.2) normal (0, 0, 1) x axis (1, 0, 0)
  line L1 (-10.2, 15.9) -> (-12.6, 15.9)
  line L2 (-10.2, 20.3) -> (-10.2, 15.9)
  line L3 (-12.6, 20.3) -> (-10.2, 20.3)
  line L4 (-12.6, 15.9) -> (-12.6, 20.3)
extrude "Extrude37" add sketch "Sketch37" along normal blind 2.71
work_plane "WorkPlane38" AlongDistance -6.5 ExtraOffset 0
sketch "Sketch38" plane through (0, 0, -6.5) normal (0, 0, 1) x axis (1, 0, 0)
  line L1 (12.6, -32.1) -> (10.2, -32.1)
  line L2 (12.6, -26.5) -> (12.6, -32.1)
  line L3 (10.2, -26.5) -> (12.6, -26.5)
  line L4 (10.2, -32.1) -> (10.2, -26.5)
extrude "Extrude38" add sketch "Sketch38" along normal blind 3
work_plane "WorkPlane39" AlongDistance -9.2 ExtraOffset 0
sketch "Sketch39" plane through (0, 0, -9.2) normal (0, 0, 1) x axis (1, 0, 0)
  line L1 (12.6, -32.1) -> (10.2, -32.1)
  line L2 (12.6, -27.7) -> (12.6, -32.1)
  line L3 (10.2, -27.7) -> (12.6, -27.7)
  line L4 (10.2, -32.1) -> (10.2, -27.7)
extrude "Extrude39" add sketch "Sketch39" along normal blind 2.71
work_plane "WorkPlane40" AlongDistance -6.5 ExtraOffset 0
sketch "Sketch40" plane through (0, 0, -6.5) normal (0, 0, 1) x axis (1, 0, 0)
  line L1 (12.6, 14.7) -> (10.2, 14.7)
  line L2 (12.6, 20.3) -> (12.6, 14.7)
  line L3 (10.2, 20.3) -> (12.6, 20.3)
  line L4 (10.2, 14.7) -> (10.2, 20.3)
extrude "Extrude40" add sketch "Sketch40" along normal blind 3
work_plane "WorkPlane41" AlongDistance -9.2 ExtraOffset 0
sketch "Sketch41" plane through (0, 0, -9.2) normal (0, 0, 1) x axis (1, 0, 0)
  line L1 (12.6, 15.9) -> (10.2, 15.9)
  line L2 (12.6, 20.3) -> (12.6, 15.9)
  line L3 (10.2, 20.3) -> (12.6, 20.3)
  line L4 (10.2, 15.9) -> (10.2, 20.3)
extrude "Extrude41" add sketch "Sketch41" along normal blind 2.71
fillet "Fillet4" radius 1.2
sketch "Sketch42" plane through (0, 0, 0) normal (1, 0, 0) x axis (0, 0, -1)
  circle C1 centre (7.7, -30.3) radius 0.55
extrude "Extrude42" cut sketch "Sketch42" distance 13.6
sketch "Sketch43" plane through (0, 0, 0) normal (1, 0, 0) x axis (0, 0, -1)
  circle C1 centre (7.7, 18.5) radius 0.55
extrude "Extrude43" cut sketch "Sketch43" distance 13.6
work_plane "WorkPlane1" AlongDistance -9.2 ExtraOffset 0
sketch "Sketch1" plane through (0, 0, -9.2) normal (0, 0, 1) x axis (1, 0, 0)
  line L1 (24.2, -27.5) -> (-24.2, -27.5)
  line L2 (24.2, 15.7) -> (24.2, -27.5)
  line L3 (-24.2, 15.7) -> (24.2, 15.7)
  line L4 (-24.2, -27.5) -> (-24.2, 15.7)
extrude "Extrude1" new body sketch "Sketch1" along normal blind 2.7
fillet "Fillet1" radius 5
fillet "Fillet2" radius 0.6
work_plane "WorkPlane2" AlongDistance -8 ExtraOffset 0
sketch "Sketch2" plane through (0, 0, -8) normal (0, 0, 1) x axis (1, 0, 0)
  line L1 (22.2, -25.5) -> (-22.2, -25.5)
  line L2 (22.2, 13.7) -> (22.2, -25.5)
  line L3 (-22.2, 13.7) -> (22.2, 13.7)
  line L4 (-22.2, -25.5) -> (-22.2, 13.7)
extrude "Extrude2" cut sketch "Sketch2" along normal blind 1.51
fillet "Fillet3" radius 1.7
work_plane "WorkPlane3" AlongDistance -8.01 ExtraOffset 0
sketch "Sketch3" plane through (0, 0, -8.01) normal (0, 0, 1) x axis (1, 0, 0)
  line L1 (21.95, -0.5) -> (20.95, -0.5)
  line L2 (21.95, 4) -> (21.95, -0.5)
  line L3 (20.95, 4) -> (21.95, 4)
  line L4 (20.95, -0.5) -> (20.95, 4)
extrude "Extrude3" add sketch "Sketch3" along normal blind 2.51
work_plane "WorkPlane4" AlongDistance -8.01 ExtraOffset 0
sketch "Sketch4" plane through (0, 0, -8.01) normal (0, 0, 1) x axis (1, 0, 0)
  line L1 (19, 12.6) -> (11, 12.6)
  line L2 (19, 13.55) -> (19, 12.6)
  line L3 (11, 13.55) -> (19, 13.55)
  line L4 (11, 12.6) -> (11, 13.55)
extrude "Extrude4" add sketch "Sketch4" along normal blind 3.11
work_plane "WorkPlane5" AlongDistance -5.8 ExtraOffset 0
sketch "Sketch5" plane through (0, 0, -5.8) normal (0, 0, 1) x axis (1, 0, 0)
  line L1 (19, 13.5) -> (11, 13.5)
  line L2 (19, 14.35) -> (19, 13.5)
  line L3 (11, 14.35) -> (19, 14.35)
  line L4 (11, 13.5) -> (11, 14.35)
extrude "Extrude5" add sketch "Sketch5" along normal blind 0.75
work_plane "WorkPlane6" AlongDistance -8.01 ExtraOffset 0
sketch "Sketch6" plane through (0, 0, -8.01) normal (0, 0, 1) x axis (1, 0, 0)
  line L1 (-21.25, -20) -> (-22.15, -20)
  line L2 (-21.25, -14) -> (-21.25, -20)
  line L3 (-22.15, -14) -> (-21.25, -14)
  line L4 (-22.15, -20) -> (-22.15, -14)
extrude "Extrude6" add sketch "Sketch6" along normal blind 6.91
work_plane "WorkPlane7" AlongDistance -3.1 ExtraOffset 0
sketch "Sketch7" plane through (0, 0, -3.1) normal (0, 0, 1) x axis (1, 0, 0)
  line L1 (-22.14, -19.7) -> (-22.4, -19.7)
  line L2 (-22.14, -14.3) -> (-22.14, -19.7)
  line L3 (-22.4, -14.3) -> (-22.14, -14.3)
  line L4 (-22.4, -19.7) -> (-22.4, -14.3)
extrude "Extrude7" add sketch "Sketch7" along normal blind 0.2
work_plane "WorkPlane8" AlongDistance -2.9 ExtraOffset 0
sketch "Sketch8" plane through (0, 0, -2.9) normal (0, 0, 1) x axis (1, 0, 0)
  line L1 (-22.14, -19.7) -> (-22.65, -19.7)
  line L2 (-22.14, -14.3) -> (-22.14, -19.7)
  line L3 (-22.65, -14.3) -> (-22.14, -14.3)
  line L4 (-22.65, -19.7) -> (-22.65, -14.3)
extrude "Extrude8" add sketch "Sketch8" along normal blind 0.5
work_plane "WorkPlane9" AlongDistance -2.4 ExtraOffset 0
sketch "Sketch9" plane through (0, 0, -2.4) normal (0, 0, 1) x axis (1, 0, 0)
  line L1 (-22.14, -19.7) -> (-22.48, -19.7)
  line L2 (-22.14, -14.3) -> (-22.14, -19.7)
  line L3 (-22.48, -14.3) -> (-22.14, -14.3)
  line L4 (-22.48, -19.7) -> (-22.48, -14.3)
extrude "Extrude9" add sketch "Sketch9" along normal blind 0.5
work_plane "WorkPlane10" AlongDistance -1.9 ExtraOffset 0
sketch "Sketch10" plane through (0, 0, -1.9) normal (0, 0, 1) x axis (1, 0, 0)
  line L1 (-22.14, -19.7) -> (-22.32, -19.7)
  line L2 (-22.14, -14.3) -> (-22.14, -19.7)
  line L3 (-22.32, -14.3) -> (-22.14, -14.3)
  line L4 (-22.32, -19.7) -> (-22.32, -14.3)
extrude "Extrude10" add sketch "Sketch10" along normal blind 0.5
work_plane "WorkPlane11" AlongDistance -8.01 ExtraOffset 0
sketch "Sketch11" plane through (0, 0, -8.01) normal (0, 0, 1) x axis (1, 0, 0)
  line L1 (22.15, -6.8) -> (21.25, -6.8)
  line L2 (22.15, -1.2) -> (22.15, -6.8)
  line L3 (21.25, -1.2) -> (22.15, -1.2)
  line L4 (21.25, -6.8) -> (21.25, -1.2)
extrude "Extrude11" add sketch "Sketch11" along normal blind 6.91
work_plane "WorkPlane12" AlongDistance -3.1 ExtraOffset 0
sketch "Sketch12" plane through (0, 0, -3.1) normal (0, 0, 1) x axis (1, 0, 0)
  line L1 (22.4, -6.5) -> (22.14, -6.5)
  line L2 (22.4, -1.5) -> (22.4, -6.5)
  line L3 (22.14, -1.5) -> (22.4, -1.5)
  line L4 (22.14, -6.5) -> (22.14, -1.5)
extrude "Extrude12" add sketch "Sketch12" along normal blind 0.2
work_plane "WorkPlane13" AlongDistance -2.9 ExtraOffset 0
sketch "Sketch13" plane through (0, 0, -2.9) normal (0, 0, 1) x axis (1, 0, 0)
  line L1 (22.65, -6.5) -> (22.14, -6.5)
  line L2 (22.65, -1.5) -> (22.65, -6.5)
  line L3 (22.14, -1.5) -> (22.65, -1.5)
  line L4 (22.14, -6.5) -> (22.14, -1.5)
extrude "Extrude13" add sketch "Sketch13" along normal blind 0.5
work_plane "WorkPlane14" AlongDistance -2.4 ExtraOffset 0
sketch "Sketch14" plane through (0, 0, -2.4) normal (0, 0, 1) x axis (1, 0, 0)
  line L1 (22.48, -6.5) -> (22.14, -6.5)
  line L2 (22.48, -1.5) -> (22.48, -6.5)
  line L3 (22.14, -1.5) -> (22.48, -1.5)
  line L4 (22.14, -6.5) -> (22.14, -1.5)
extrude "Extrude14" add sketch "Sketch14" along normal blind 0.5
work_plane "WorkPlane15" AlongDistance -1.9 ExtraOffset 0
sketch "Sketch15" plane through (0, 0, -1.9) normal (0, 0, 1) x axis (1, 0, 0)
  line L1 (22.32, -6.5) -> (22.14, -6.5)
  line L2 (22.32, -1.5) -> (22.32, -6.5)
  line L3 (22.14, -1.5) -> (22.32, -1.5)
  line L4 (22.14, -6.5) -> (22.14, -1.5)
extrude "Extrude15" add sketch "Sketch15" along normal blind 0.5
work_plane "WorkPlane16" AlongDistance -8.01 ExtraOffset 0
sketch "Sketch16" plane through (0, 0, -8.01) normal (0, 0, 1) x axis (1, 0, 0)
  circle C1 centre (20.6, 11.6) radius 0.8
extrude "Extrude16" add sketch "Sketch16" along normal blind 7.96
work_plane "WorkPlane17" AlongDistance -8.01 ExtraOffset 0
sketch "Sketch17" plane through (0, 0, -8.01) normal (0, 0, 1) x axis (1, 0, 0)
  circle C1 centre (-20.3, -10) radius 0.8
extrude "Extrude17" add sketch "Sketch17" along normal blind 7.96
work_plane "WorkPlane18" AlongDistance -8.01 ExtraOffset 0
sketch "Sketch18" plane through (0, 0, -8.01) normal (0, 0, 1) x axis (1, 0, 0)
  circle C1 centre (-1.7, -12.2) radius 0.8
extrude "Extrude18" add sketch "Sketch18" along normal blind 7.96
work_plane "WorkPlane19" AlongDistance -9.3 ExtraOffset 0
sketch "Sketch19" plane through (0, 0, -9.3) normal (0, 0, 1) x axis (1, 0, 0)
  line L1 (4, -27.6) -> (-4, -27.6)
  line L2 (4, -26.5) -> (4, -27.6)
  line L3 (-4, -26.5) -> (4, -26.5)
  line L4 (-4, -27.6) -> (-4, -26.5)
extrude "Extrude19" cut sketch "Sketch19" along normal blind 0.65
work_plane "WorkPlane20" AlongDistance -8.3 ExtraOffset 0
sketch "Sketch20" plane through (0, 0, -8.3) normal (0, 0, 1) x axis (1, 0, 0)
  circle C1 centre (11, -15.3) radius 10.3
extrude "Extrude20" cut sketch "Sketch20" along normal blind 0.31
work_plane "WorkPlane21" AlongDistance -9.2 ExtraOffset 0
sketch "Sketch21" plane through (0, 0, -9.2) normal (0, 0, 1) x axis (1, 0, 0)
  line L1 (-11.95, -9.65) -> (-15.05, -9.65)
  line L2 (-9.75, -4.35) -> (-9.75, -7.45)
  line L3 (-15.05, -2.15) -> (-11.95, -2.15)
  line L4 (-17.25, -7.45) -> (-17.25, -4.35)
  line L5 (-11.95, -9.05) -> (-15.05, -9.05)
  line L6 (-10.35, -4.35) -> (-10.35, -7.45)
  line L7 (-15.05, -2.75) -> (-11.95, -2.75)
  line L8 (-16.65, -7.45) -> (-16.65, -4.35)
  arc A1 centre (-11.95, -7.45) radius 2.2 clockwise from (-9.75, -7.45) to (-11.95, -9.65)
  arc A2 centre (-11.95, -4.35) radius 2.2 clockwise from (-11.95, -2.15) to (-9.75, -4.35)
  arc A3 centre (-15.05, -4.35) radius 2.2 clockwise from (-17.25, -4.35) to (-15.05, -2.15)
  arc A4 centre (-15.05, -7.45) radius 2.2 clockwise from (-15.05, -9.65) to (-17.25, -7.45)
  arc A5 centre (-11.95, -7.45) radius 1.6 clockwise from (-10.35, -7.45) to (-11.95, -9.05)
  arc A6 centre (-11.95, -4.35) radius 1.6 clockwise from (-11.95, -2.75) to (-10.35, -4.35)
  arc A7 centre (-15.05, -4.35) radius 1.6 clockwise from (-16.65, -4.35) to (-15.05, -2.75)
  arc A8 centre (-15.05, -7.45) radius 1.6 clockwise from (-15.05, -9.05) to (-16.65, -7.45)
extrude "Extrude21" cut sketch "Sketch21" along normal blind 0.3
work_plane "WorkPlane22" AlongDistance -9.2 ExtraOffset 0
sketch "Sketch22" plane through (0, 0, -9.2) normal (0, 0, 1) x axis (1, 0, 0)
  line L1 (-2.95, -9.65) -> (-6.05, -9.65)
  line L2 (-0.75, -4.35) -> (-0.75, -7.45)
  line L3 (-6.05, -2.15) -> (-2.95, -2.15)
  line L4 (-8.25, -7.45) -> (-8.25, -4.35)
  line L5 (-2.95, -9.05) -> (-6.05, -9.05)
  line L6 (-1.35, -4.35) -> (-1.35, -7.45)
  line L7 (-6.05, -2.75) -> (-2.95, -2.75)
  line L8 (-7.65, -7.45) -> (-7.65, -4.35)
  arc A1 centre (-2.95, -7.45) radius 2.2 clockwise from (-0.75, -7.45) to (-2.95, -9.65)
  arc A2 centre (-2.95, -4.35) radius 2.2 clockwise from (-2.95, -2.15) to (-0.75, -4.35)
  arc A3 centre (-6.05, -4.35) radius 2.2 clockwise from (-8.25, -4.35) to (-6.05, -2.15)
  arc A4 centre (-6.05, -7.45) radius 2.2 clockwise from (-6.05, -9.65) to (-8.25, -7.45)
  arc A5 centre (-2.95, -7.45) radius 1.6 clockwise from (-1.35, -7.45) to (-2.95, -9.05)
  arc A6 centre (-2.95, -4.35) radius 1.6 clockwise from (-2.95, -2.75) to (-1.35, -4.35)
  arc A7 centre (-6.05, -4.35) radius 1.6 clockwise from (-7.65, -4.35) to (-6.05, -2.75)
  arc A8 centre (-6.05, -7.45) radius 1.6 clockwise from (-6.05, -9.05) to (-7.65, -7.45)
extrude "Extrude22" cut sketch "Sketch22" along normal blind 0.3
work_plane "WorkPlane23" AlongDistance -9.2 ExtraOffset 0
sketch "Sketch23" plane through (0, 0, -9.2) normal (0, 0, 1) x axis (1, 0, 0)
  line L1 (-5.7, -7.9) -> (-6.5, -7.9)
  line L2 (-5.7, -7.1) -> (-5.7, -7.9)
  line L3 (-6.5, -7.1) -> (-5.7, -7.1)
  line L4 (-6.5, -7.9) -> (-6.5, -7.1)
  line L5 (-4.1, -7.9) -> (-4.9, -7.9)
  line L6 (-4.1, -7.1) -> (-4.1, -7.9)
  line L7 (-4.9, -7.1) -> (-4.1, -7.1)
  line L8 (-4.9, -7.9) -> (-4.9, -7.1)
  line L9 (-2.5, -7.9) -> (-3.3, -7.9)
  line L10 (-2.5, -7.1) -> (-2.5, -7.9)
  line L11 (-3.3, -7.1) -> (-2.5, -7.1)
  line L12 (-3.3, -7.9) -> (-3.3, -7.1)
  line L13 (-5.7, -6.3) -> (-6.5, -6.3)
  line L14 (-5.7, -5.5) -> (-5.7, -6.3)
  line L15 (-6.5, -5.5) -> (-5.7, -5.5)
  line L16 (-6.5, -6.3) -> (-6.5, -5.5)
  line L17 (-4.1, -6.3) -> (-4.9, -6.3)
  line L18 (-4.1, -5.5) -> (-4.1, -6.3)
  line L19 (-4.9, -5.5) -> (-4.1, -5.5)
  line L20 (-4.9, -6.3) -> (-4.9, -5.5)
  line L21 (-2.5, -6.3) -> (-3.3, -6.3)
  line L22 (-2.5, -5.5) -> (-2.5, -6.3)
  line L23 (-3.3, -5.5) -> (-2.5, -5.5)
  line L24 (-3.3, -6.3) -> (-3.3, -5.5)
  line L25 (-5.7, -4.7) -> (-6.5, -4.7)
  line L26 (-5.7, -3.9) -> (-5.7, -4.7)
  line L27 (-6.5, -3.9) -> (-5.7, -3.9)
  line L28 (-6.5, -4.7) -> (-6.5, -3.9)
  line L29 (-4.1, -4.7) -> (-4.9, -4.7)
  line L30 (-4.1, -3.9) -> (-4.1, -4.7)
  line L31 (-4.9, -3.9) -> (-4.1, -3.9)
  line L32 (-4.9, -4.7) -> (-4.9, -3.9)
  line L33 (-2.5, -4.7) -> (-3.3, -4.7)
  line L34 (-2.5, -3.9) -> (-2.5, -4.7)
  line L35 (-3.3, -3.9) -> (-2.5, -3.9)
  line L36 (-3.3, -4.7) -> (-3.3, -3.9)
extrude "Extrude23" cut sketch "Sketch23" along normal blind 0.3
work_plane "WorkPlane24" AlongDistance -9.2 ExtraOffset 0
sketch "Sketch24" plane through (0, 0, -9.2) normal (0, 0, 1) x axis (1, 0, 0)
  line L1 (6.05, -9.65) -> (2.95, -9.65)
  line L2 (8.25, -4.35) -> (8.25, -7.45)
  line L3 (2.95, -2.15) -> (6.05, -2.15)
  line L4 (0.75, -7.45) -> (0.75, -4.35)
  line L5 (6.05, -9.05) -> (2.95, -9.05)
  line L6 (7.65, -4.35) -> (7.65, -7.45)
  line L7 (2.95, -2.75) -> (6.05, -2.75)
  line L8 (1.35, -7.45) -> (1.35, -4.35)
  arc A1 centre (6.05, -7.45) radius 2.2 clockwise from (8.25, -7.45) to (6.05, -9.65)
  arc A2 centre (6.05, -4.35) radius 2.2 clockwise from (6.05, -2.15) to (8.25, -4.35)
  arc A3 centre (2.95, -4.35) radius 2.2 clockwise from (0.75, -4.35) to (2.95, -2.15)
  arc A4 centre (2.95, -7.45) radius 2.2 clockwise from (2.95, -9.65) to (0.75, -7.45)
  arc A5 centre (6.05, -7.45) radius 1.6 clockwise from (7.65, -7.45) to (6.05, -9.05)
  arc A6 centre (6.05, -4.35) radius 1.6 clockwise from (6.05, -2.75) to (7.65, -4.35)
  arc A7 centre (2.95, -4.35) radius 1.6 clockwise from (1.35, -4.35) to (2.95, -2.75)
  arc A8 centre (2.95, -7.45) radius 1.6 clockwise from (2.95, -9.05) to (1.35, -7.45)
extrude "Extrude24" cut sketch "Sketch24" along normal blind 0.3
work_plane "WorkPlane25" AlongDistance -9.2 ExtraOffset 0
